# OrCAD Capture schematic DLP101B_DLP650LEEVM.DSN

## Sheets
1 PAGE-07 Important Notice
2 PAGE-06 Revisions
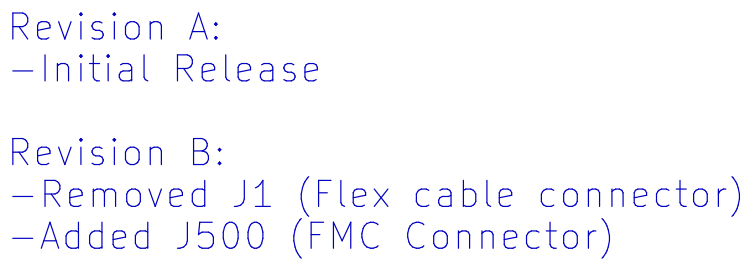
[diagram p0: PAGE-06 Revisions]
3 PAGE-05  DLPA200 Reset Driver: size A3
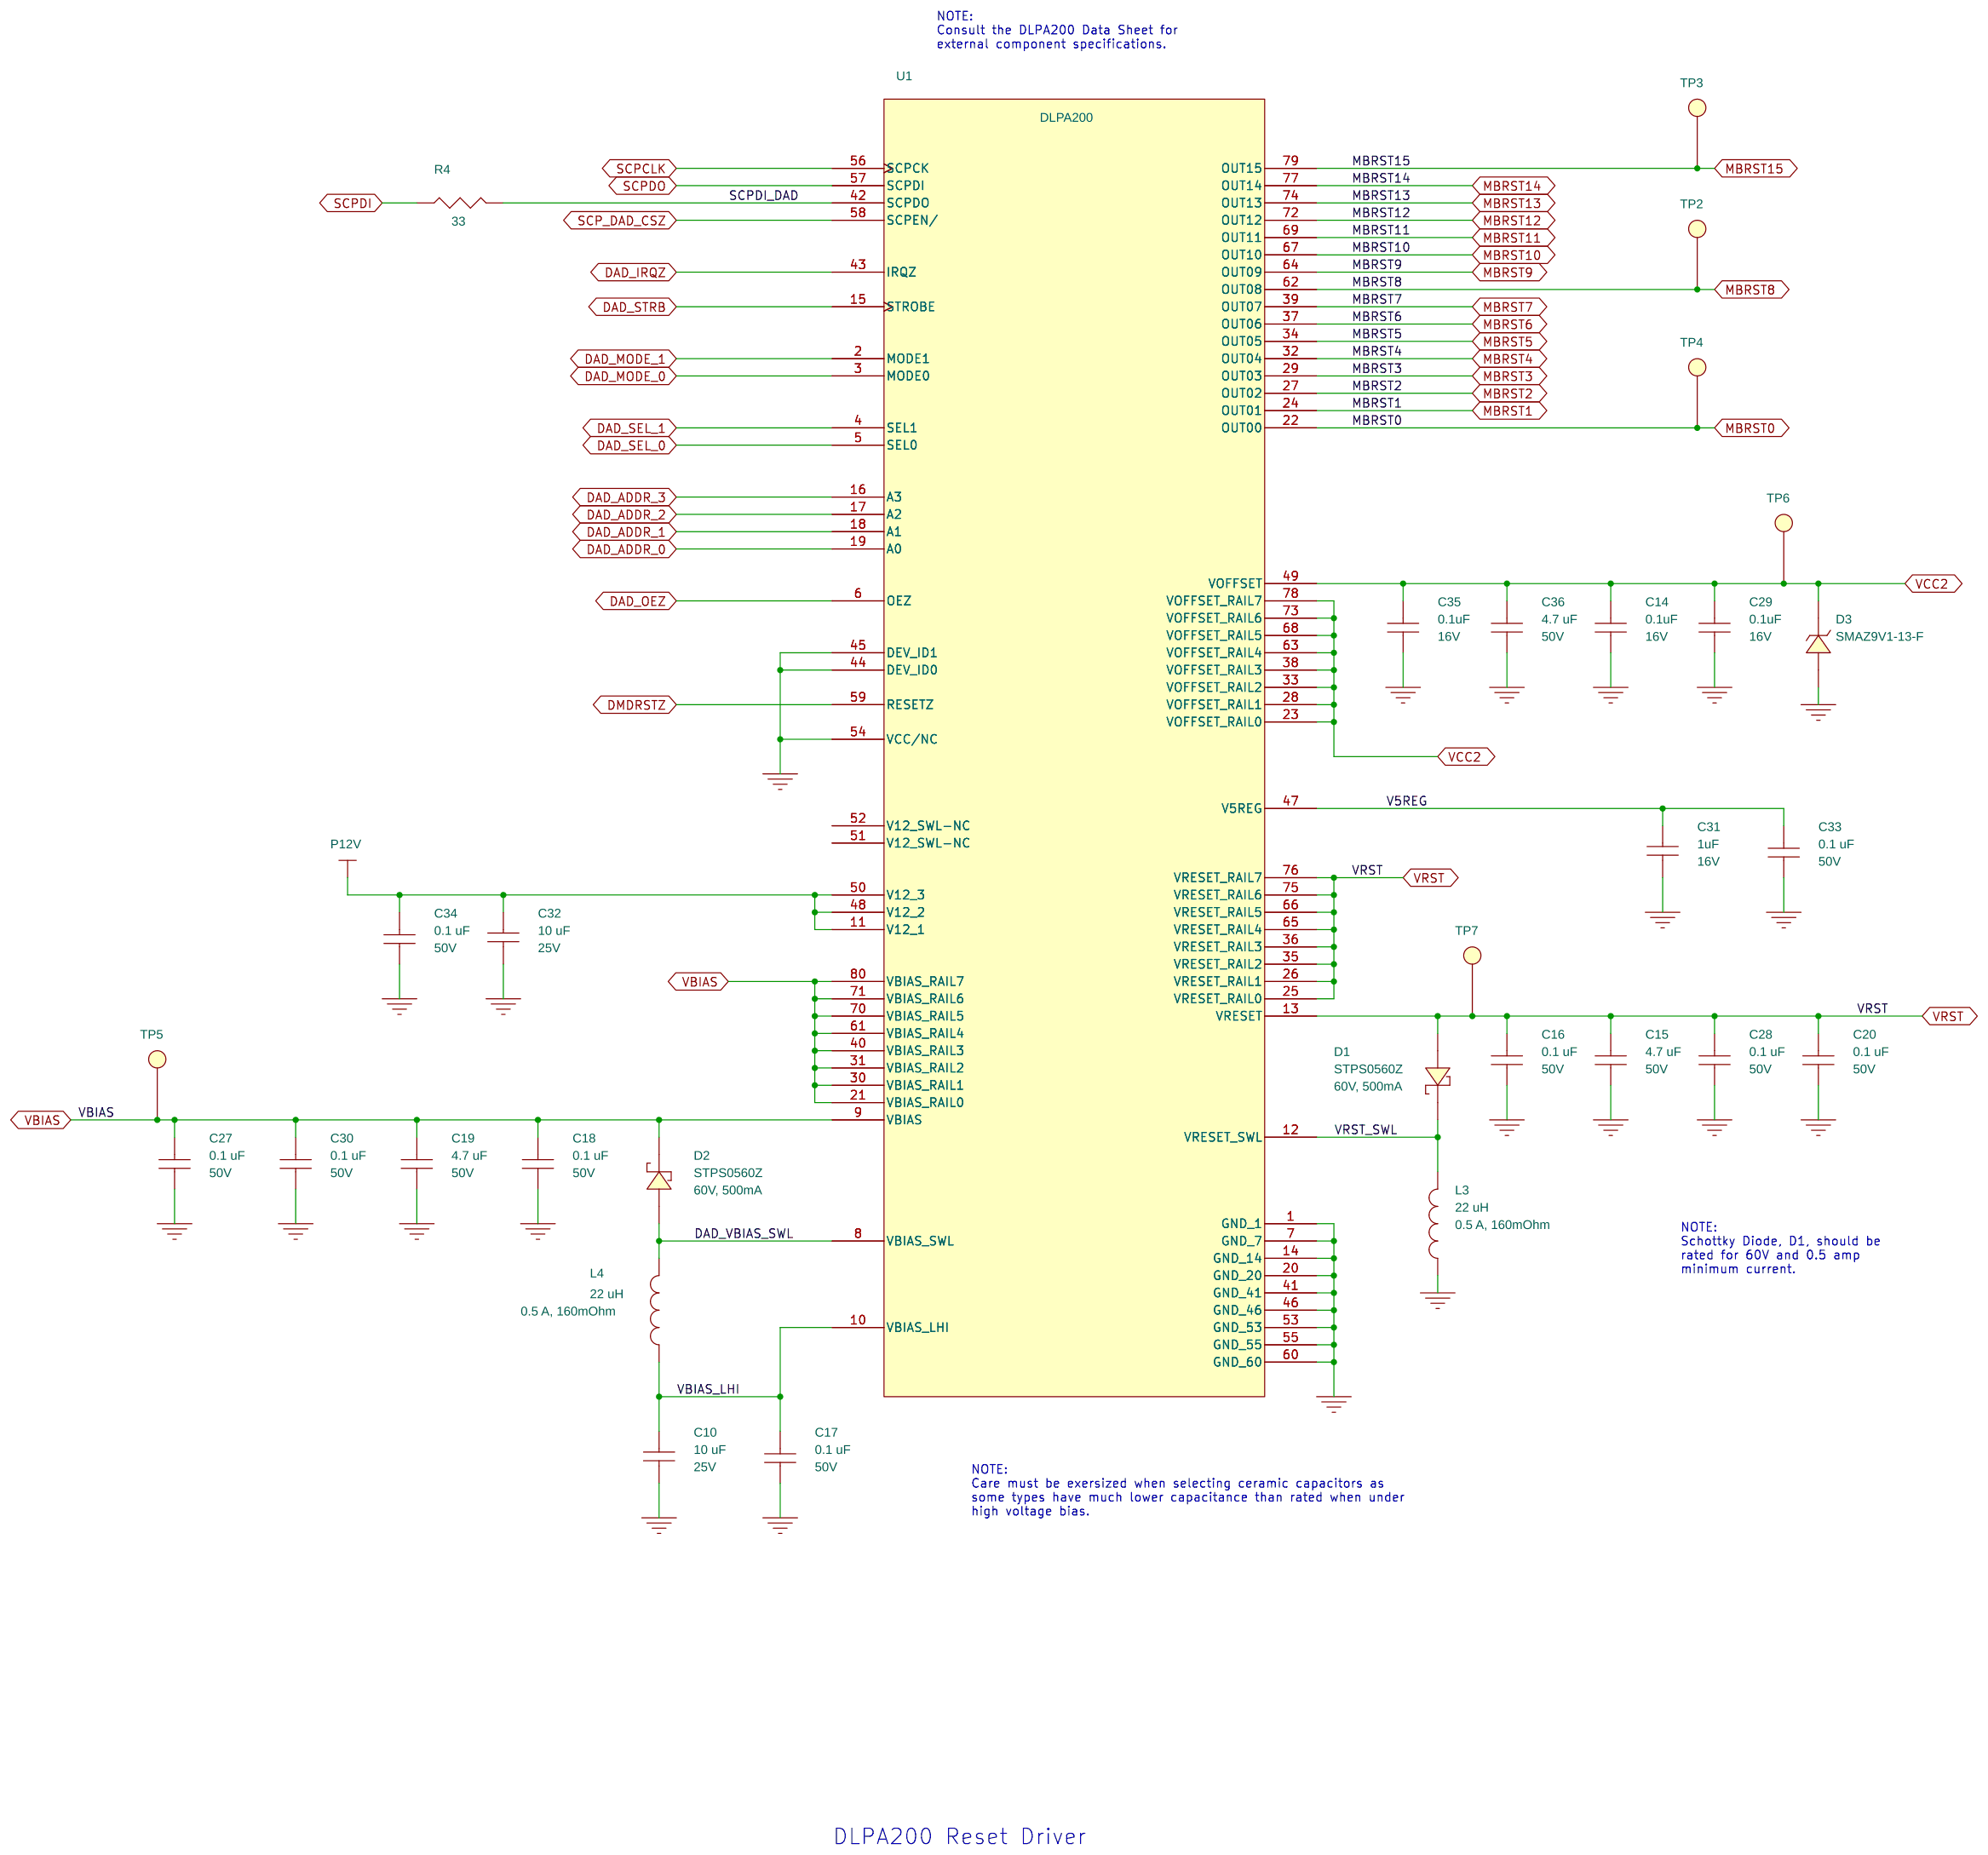
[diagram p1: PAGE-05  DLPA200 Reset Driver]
4 PAGE-01  TITLE: rev: D
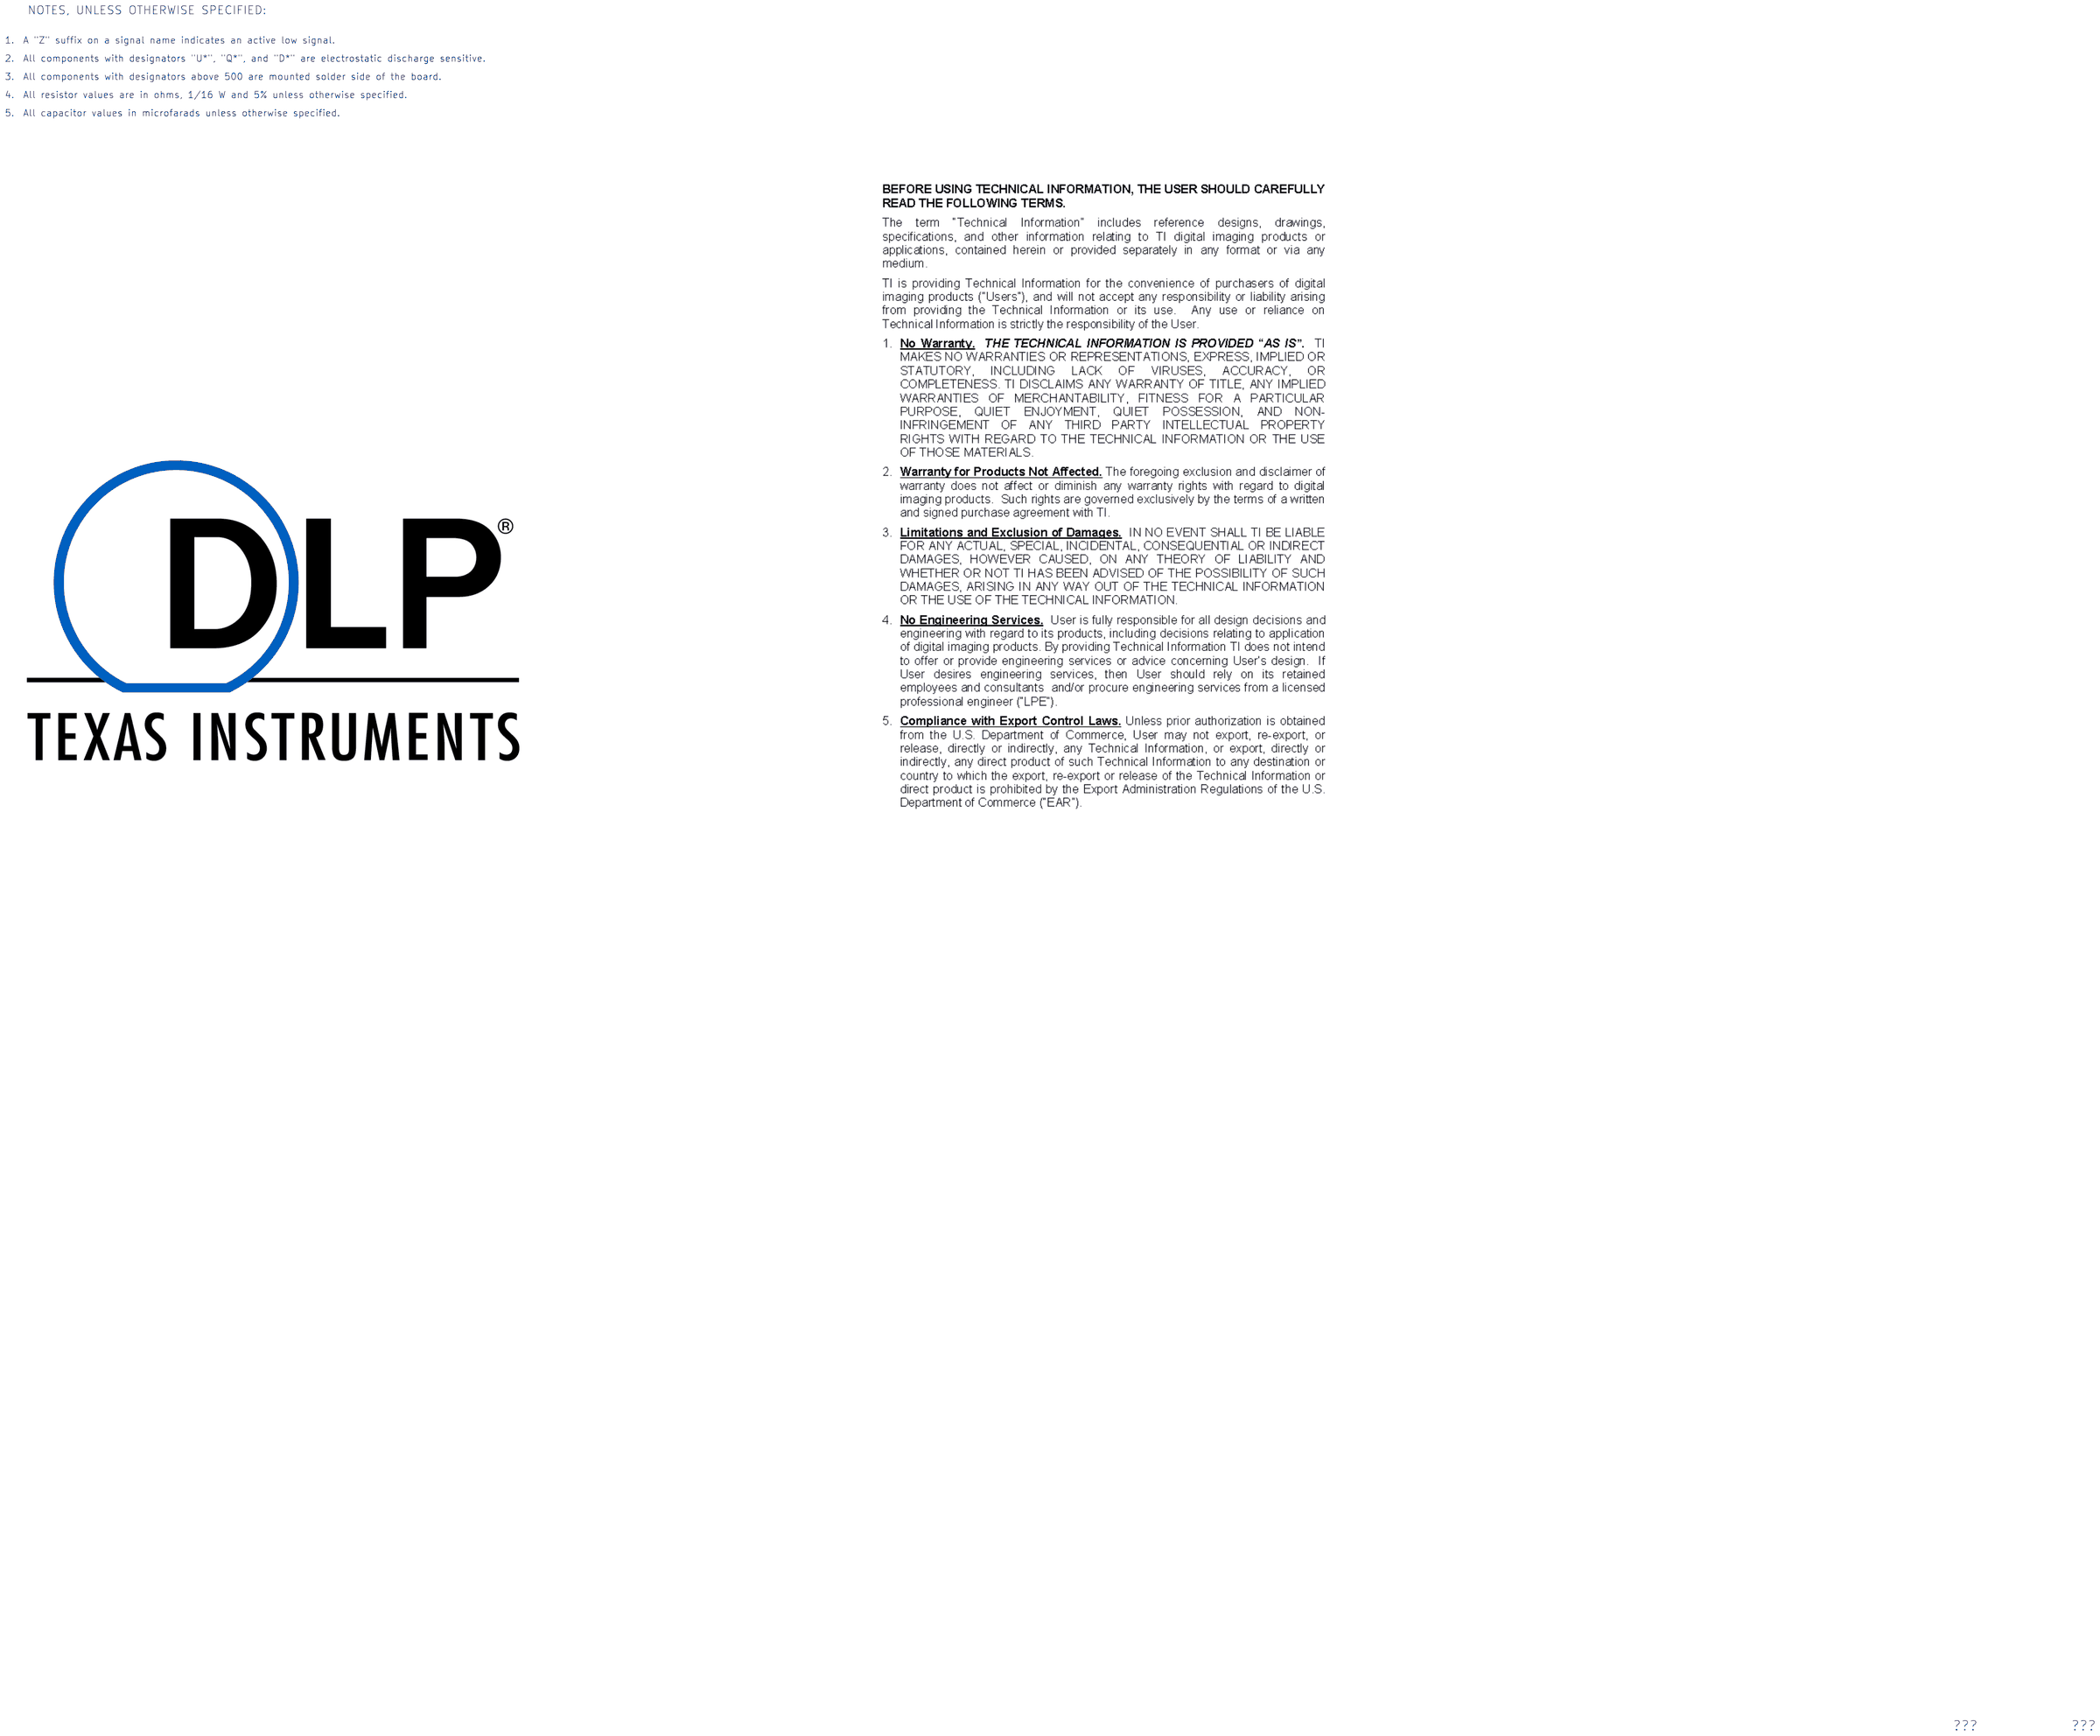
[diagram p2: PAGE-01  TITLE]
5 PAGE-02  Block Diagram
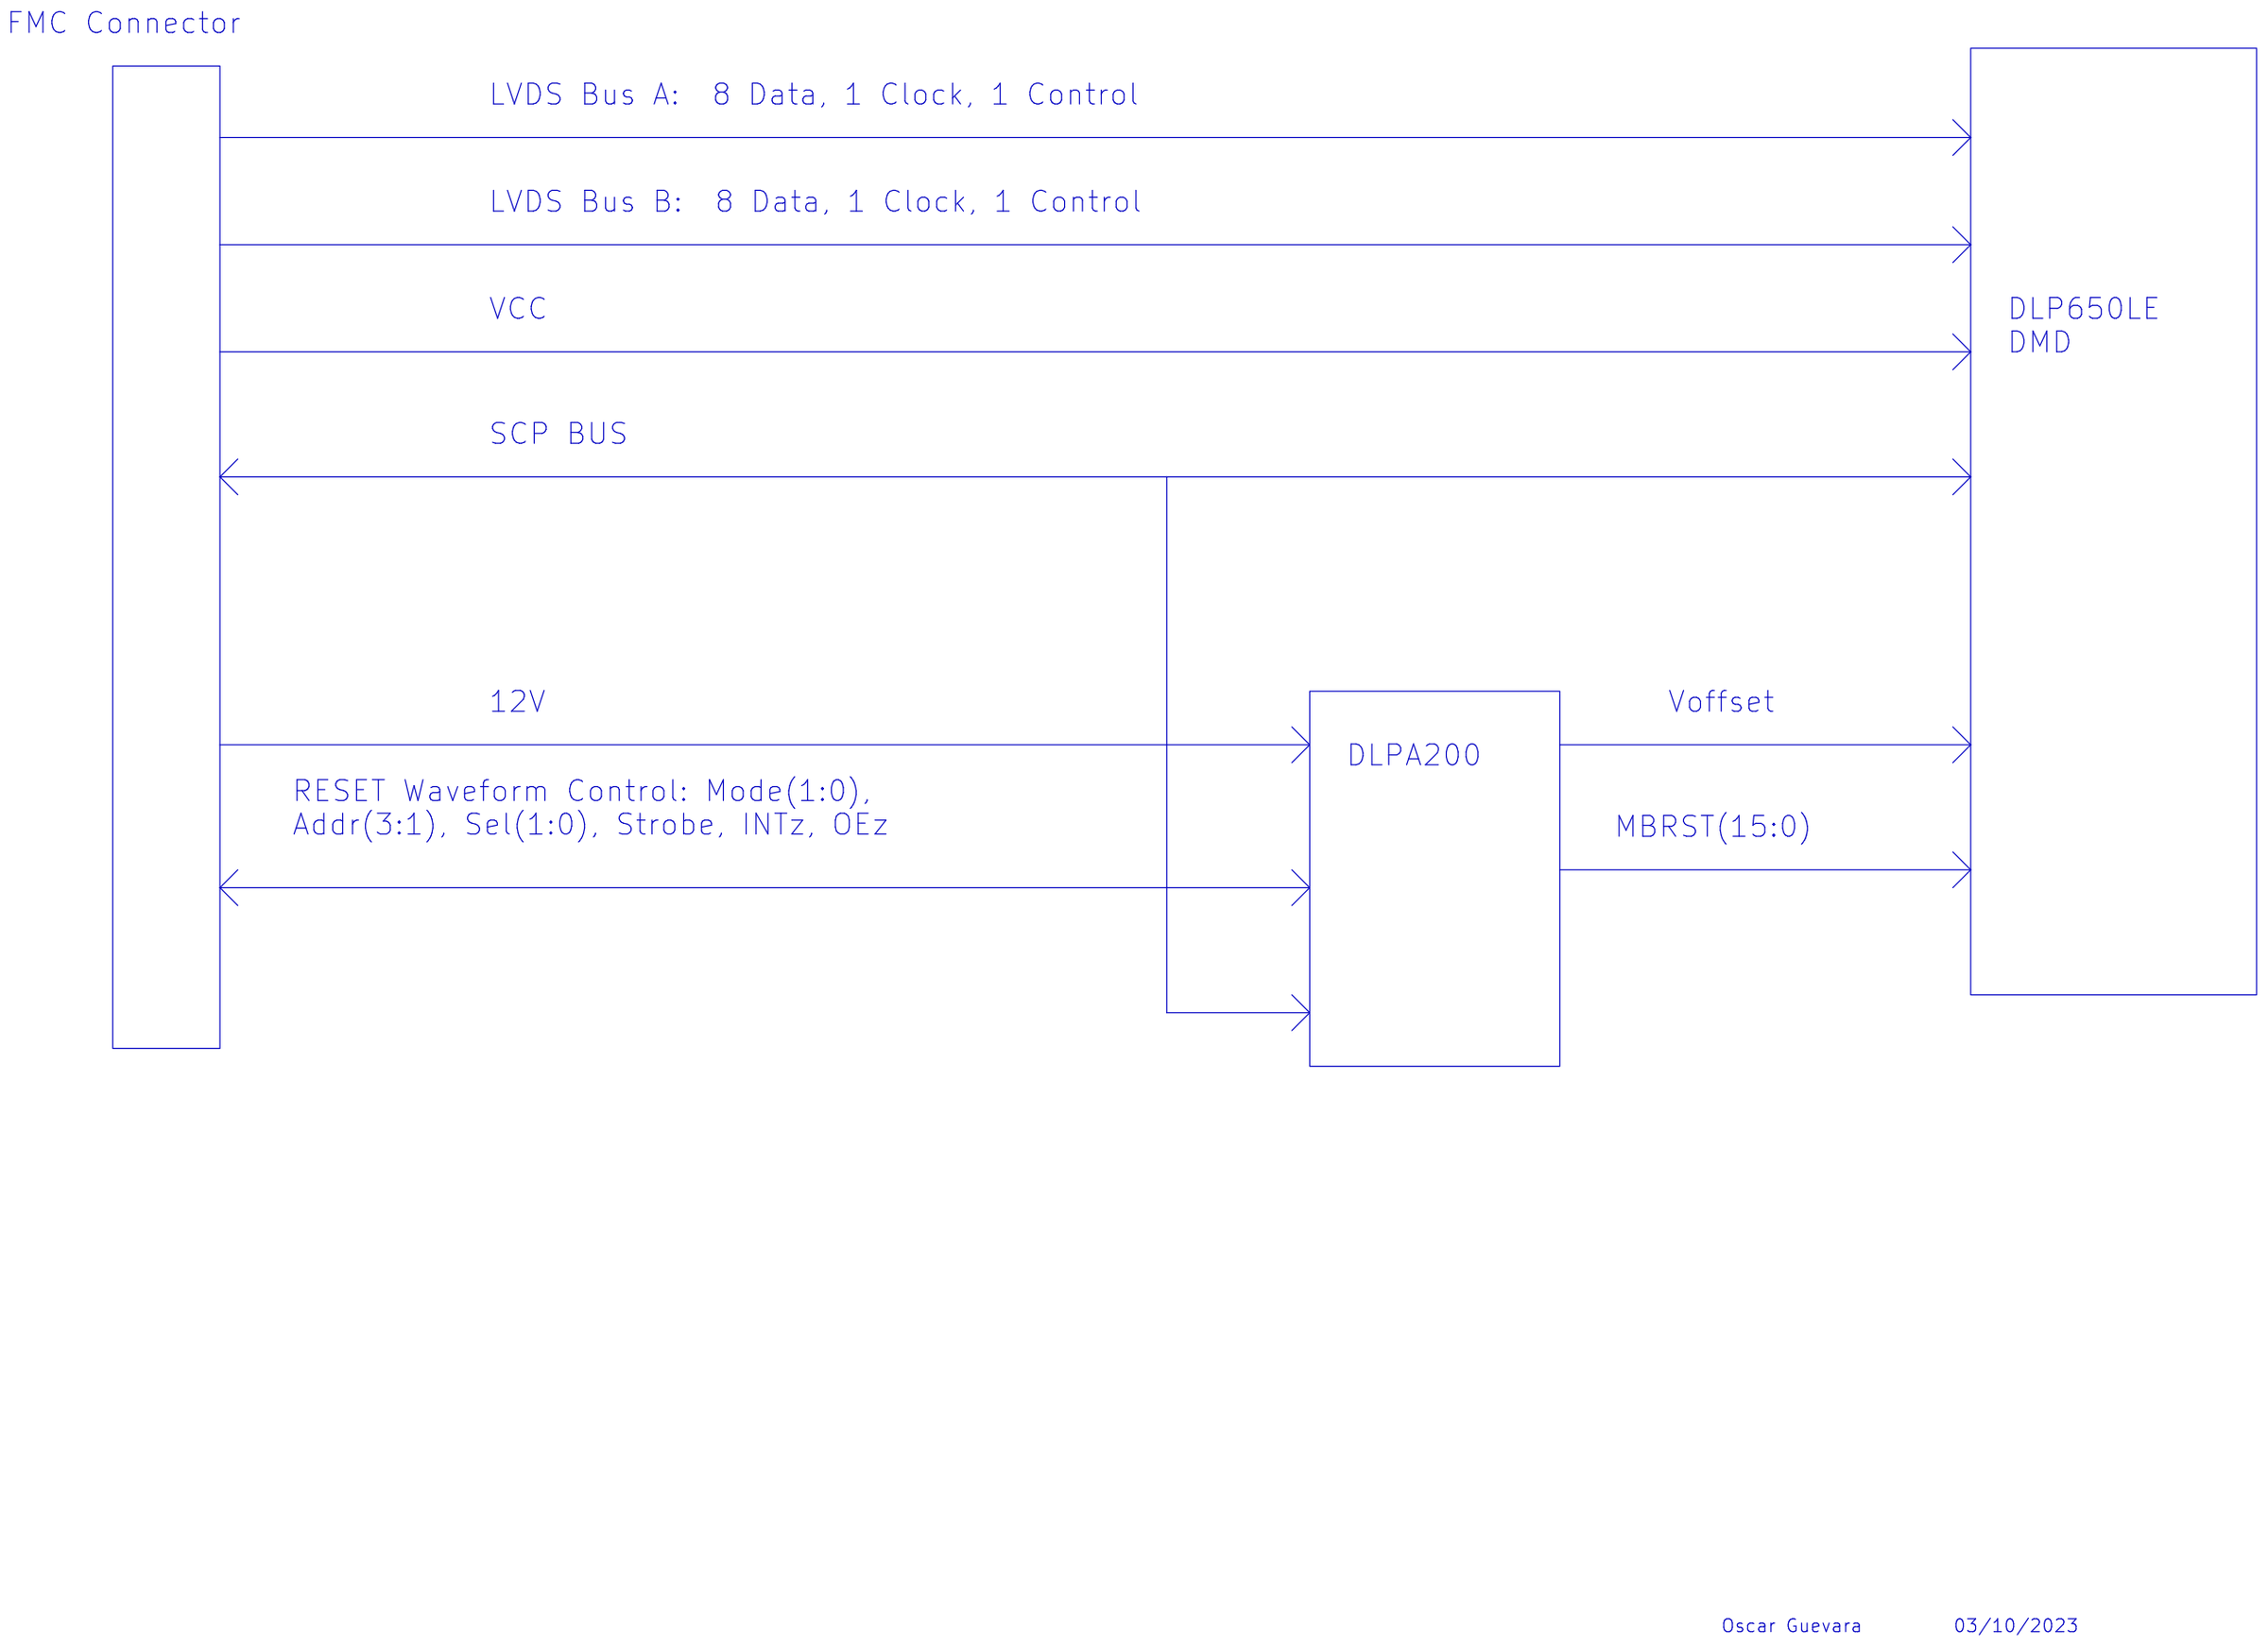
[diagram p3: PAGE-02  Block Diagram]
6 PAGE-04  Series 450 DMD: size A3
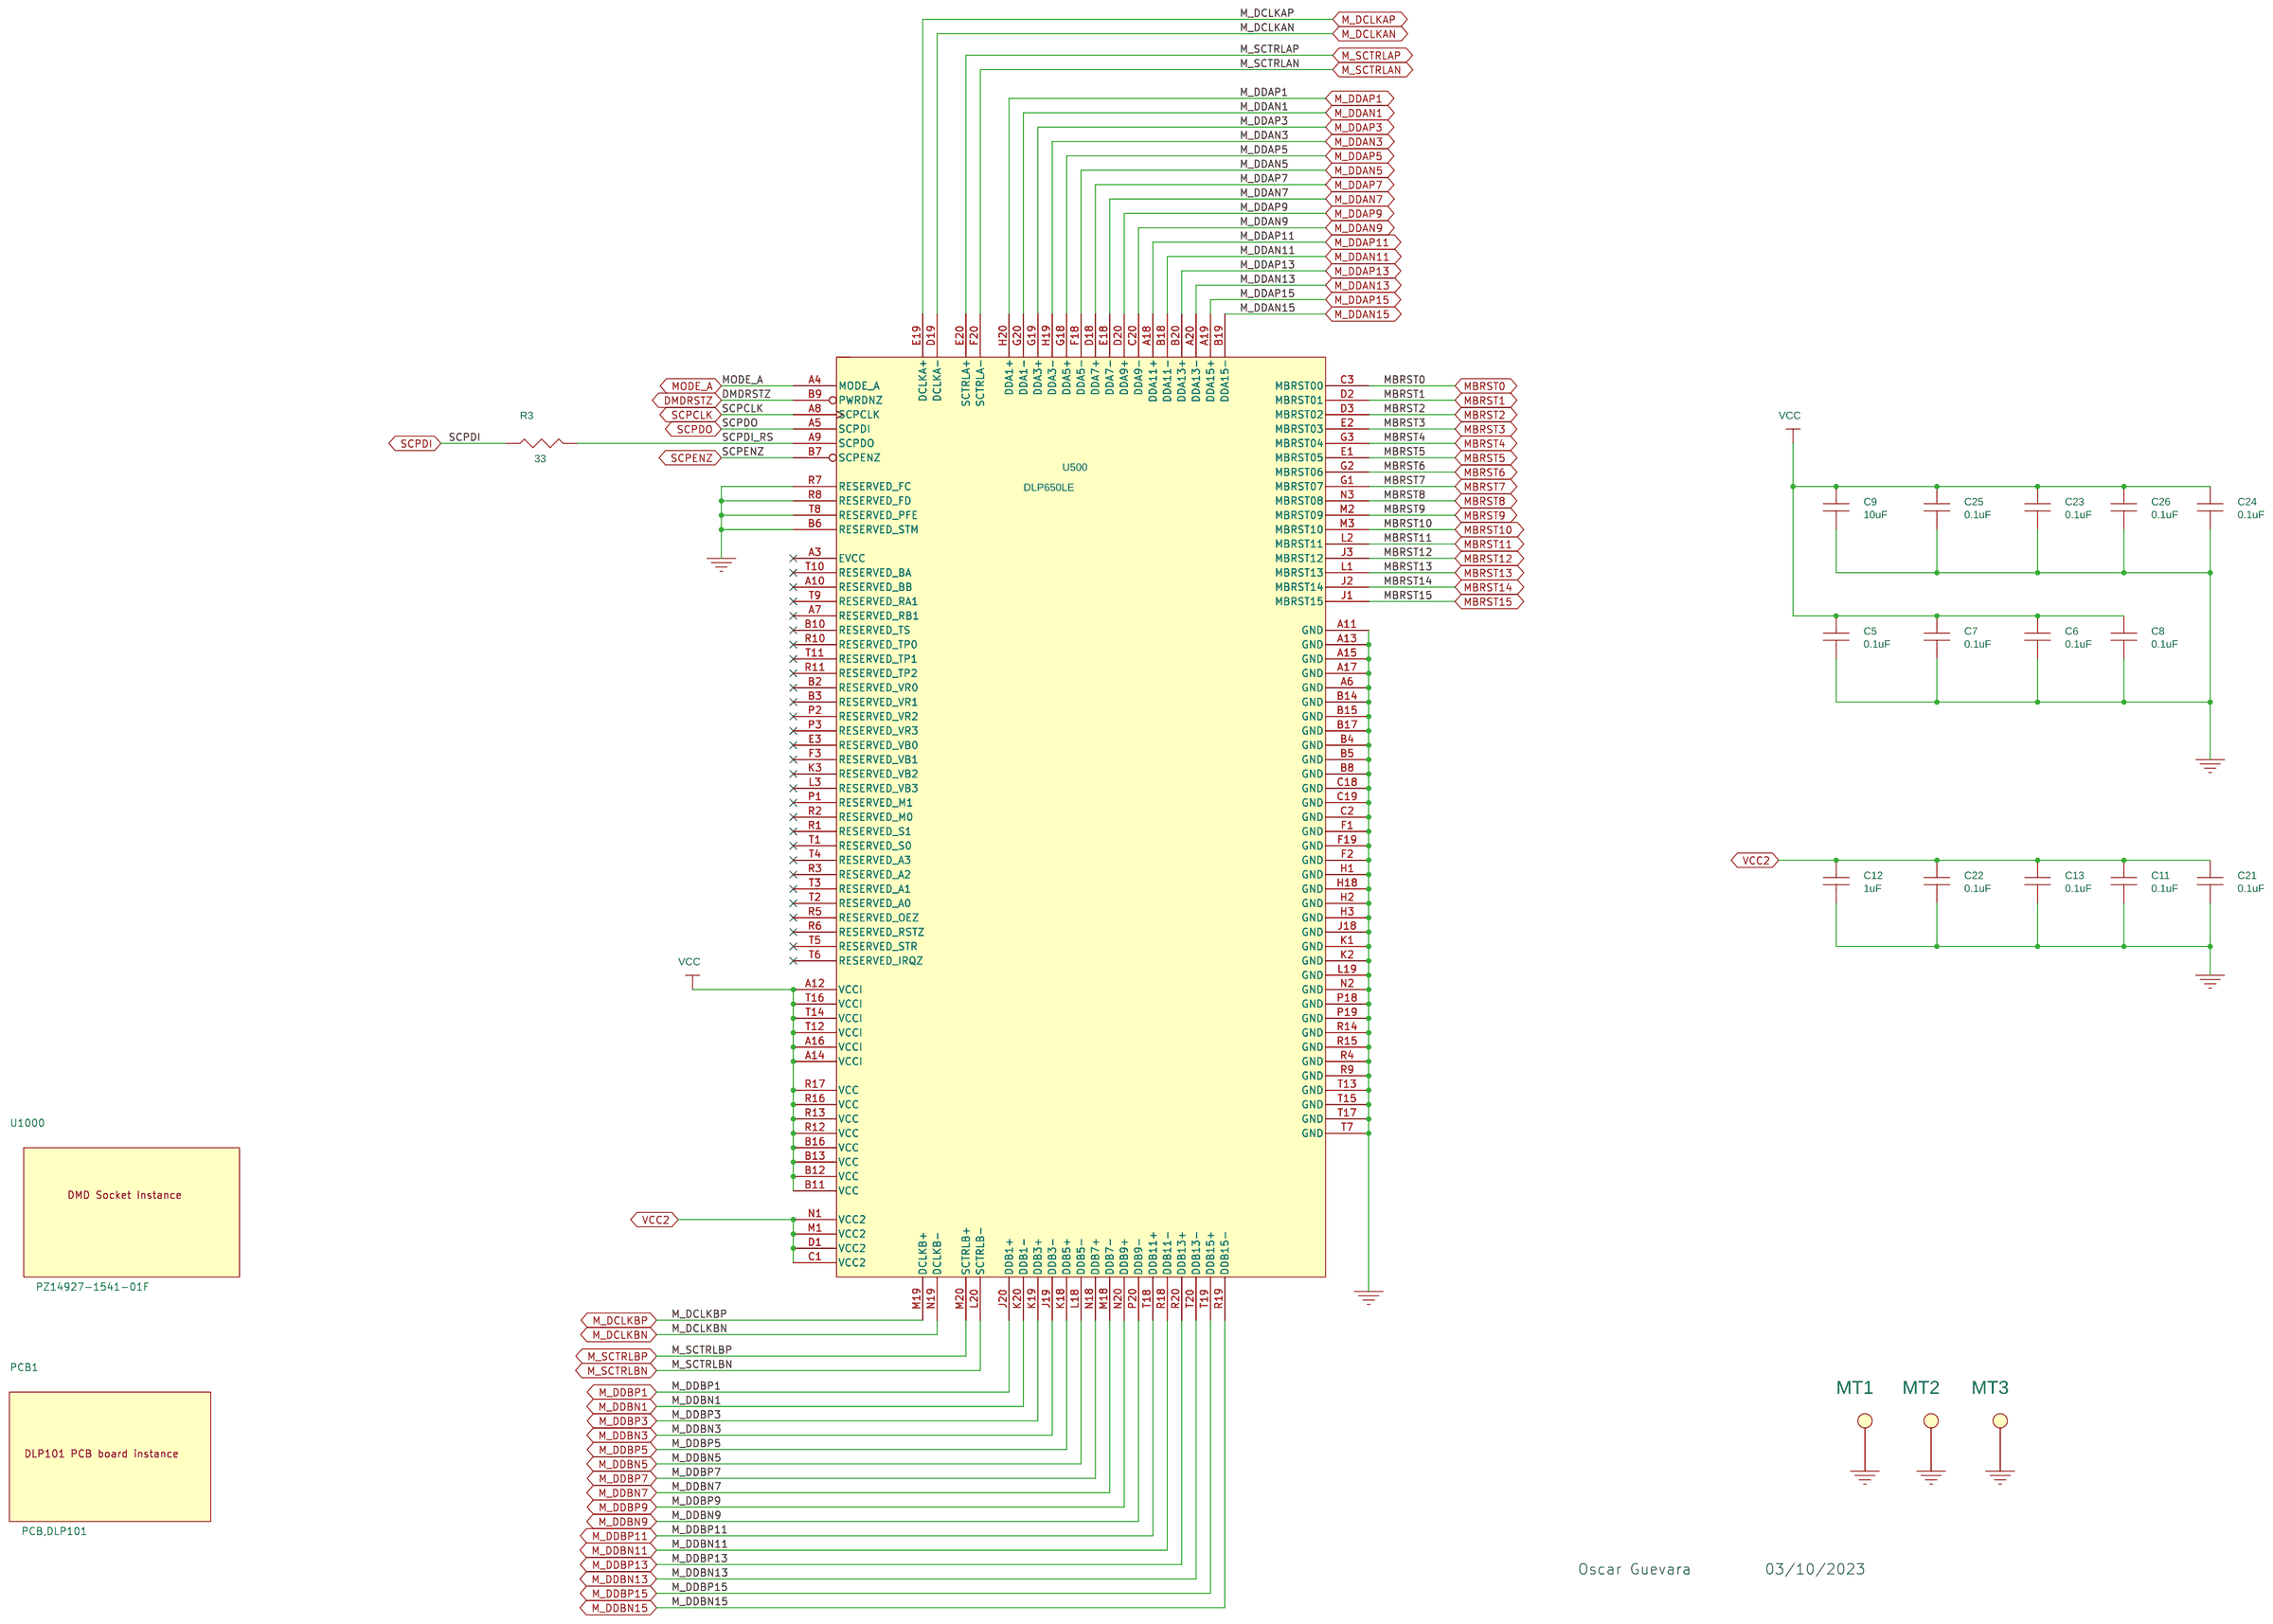
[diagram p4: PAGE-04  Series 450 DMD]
7 PAGE-03  FMC Connector: size A2
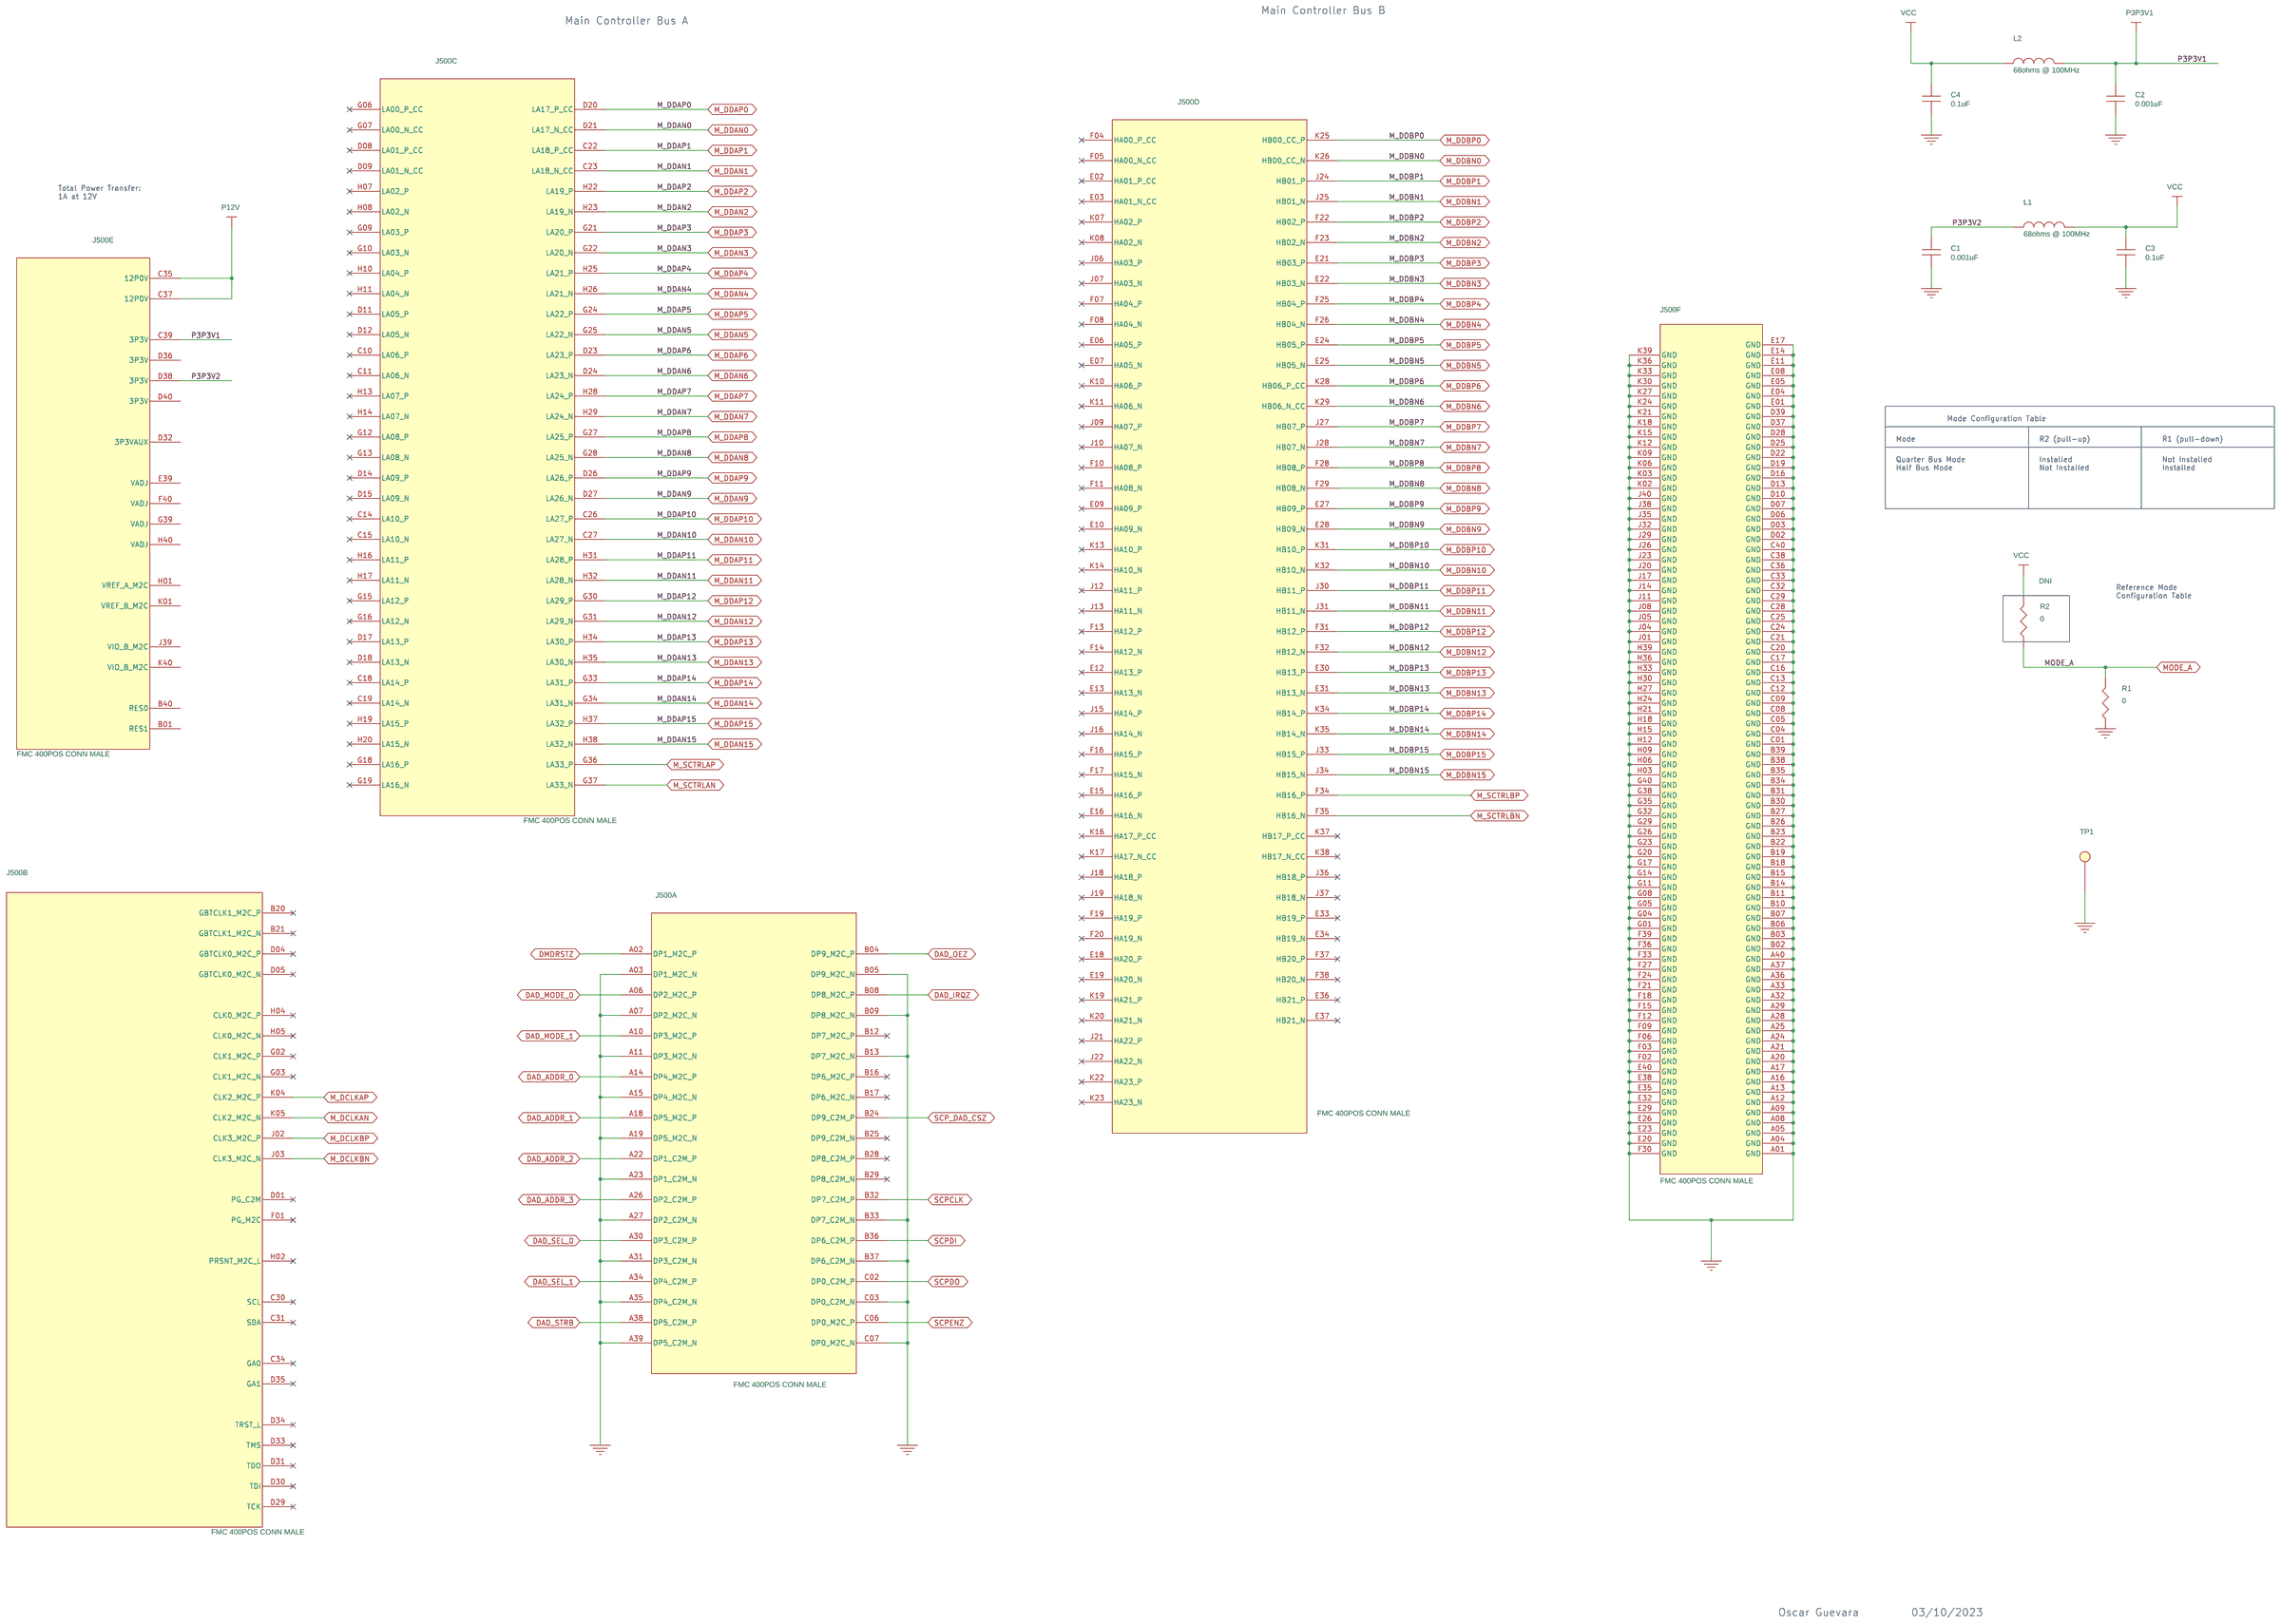
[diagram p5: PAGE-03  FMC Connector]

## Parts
sheet PAGE-03  FMC Connector
C1  0.001uF  [0603AVX]
C2  0.001uF  [0603AVX]
C3  0.1uF  [0603AVX]
C4  0.1uF  [0603AVX]
J500  FMC 400POS CONN MALE  [CONN400-SEAM-40-A-A_SAM-ALPHA]  (sections A,B,C,D,E,F)
L1  68ohms @ 100MHz  [0603AVX]
L2  68ohms @ 100MHz  [0603AVX]
R1  0  [0603AVX]
R2  0  [0603AVX]
TP1  Testpoint  [TP40_24]
sheet PAGE-04  Series 450 DMD
C5  0.1uF  [0603AVX]
C6  0.1uF  [0603AVX]
C7  0.1uF  [0603AVX]
C8  0.1uF  [0603AVX]
C9  10uF  [1206AVX]
C11  0.1uF  [0603AVX]
C12  1uF  [0603AVX]
C13  0.1uF  [0603AVX]
C21  0.1uF  [0603AVX]
C22  0.1uF  [0603AVX]
C23  0.1uF  [0603AVX]
C24  0.1uF  [0603AVX]
C25  0.1uF  [0603AVX]
C26  0.1uF  [0603AVX]
MT1  MT2  [MT2]
MT2  MT2  [MT2]
MT3  MT2  [MT2]
PCB1  PCB,DLP101
R3  33  [0603AVX]
U500  DLP650LE  [DMD_S450]
U1000  PZ14927-1541-01F  [DMD_S450]
sheet PAGE-05  DLPA200 Reset Driver
C10  10 uF  [CAP_1210]
C14  0.1uF  [0603AVX]
C15  4.7 uF  [CAP_1812]
C16  0.1 uF  [CAP_0805]
C17  0.1 uF  [CAP_0805]
C18  0.1 uF  [CAP_0805]
C19  4.7 uF  [CAP_1812]
C20  0.1 uF  [CAP_0805]
C27  0.1 uF  [CAP_0805]
C28  0.1 uF  [CAP_0805]
C29  0.1uF  [0603AVX]
C30  0.1 uF  [CAP_0805]
C31  1uF  [0603AVX]
C32  10 uF  [CAP_1210]
C33  0.1 uF  [CAP_0805]
C34  0.1 uF  [CAP_0805]
C35  0.1uF  [0603AVX]
C36  4.7 uF  [CAP_1812]
D1  DIODE_SCHOTTKY  [SOD_123]
D2  DIODE_SCHOTTKY  [SOD_123]
D3  9.1V  [DO-214AC]
L3  22 uH  [IND_DT1608C]
L4  22 uH  [IND_DT1608C]
R4  33  [0603AVX]
TP2  Testpoint  [TP40_24]
TP3  Testpoint  [TP40_24]
TP4  Testpoint  [TP40_24]
TP5  Testpoint  [TP40_24]
TP6  Testpoint  [TP40_24]
TP7  Testpoint  [TP40_24]
U1  DLPA200  [TQFP80_5MM]

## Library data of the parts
C1 C2 = CAP_NP: Capacitor; CCA ITEM: 3; MFG: AVX; Part Number: 06035C102KAT2A; Rating: 50V; Tolerance: 10%; Type: X7R
C3-C8 C11 C13 C21-C26 = CAP_NP: Capacitor; CCA ITEM: 1; MFG: AVX; Part Number: 0603YC104KAT2A; Rating: 16V; Tolerance: 10%; Type: X7R
J500 = FMC_400POS_CONNECTOR: MFG: Samtec; PART NUMBER: SEAM-40-11.0-S-10-2-A-K-TR
L1 L2 = INDUCTOR: Ferrite; CCA ITEM: 11; MFG: Steward; Part Number: MI0603J680R-10
R1 = R: Resistor; CCA ITEM: 14; MFG: Yageo; Part Number: RC0603JR-070RL; Rating: 1/10W
R2 = R: Resistor; CCA ITEM: 14; MFG: Yageo; Note: DNI; Part Number: RC0603JR-070RL; Rating: 1/10W
TP1-TP7 = Testpoint: Test point
C9 = CAP_NP: Capacitor; CCA ITEM: 7; MFG: Samsung Electro-Mechanics; Part Number: CL31B106KAHNNNE; Rating: 25V; Tolerance: 10%; Type: X7R
C12 = CAP_NP: Capacitor; CCA ITEM: 6; MFG: Samsung Electro-Mechanics; Part Number: CL10B105KO8NNNC; Rating: 16V; Tolerance: 10%; Type: X7R
MT1-MT3 = Testpoint: Test point; DNI: DNI
PCB1 = DLP026_5
R3 R4 = R: Resistor; CCA ITEM: 13; MFG: Yageo; Part Number: RC0603FR-0733RL; Rating: 1/10W; Tolerance: 1%
U500 = Series_450_DMD: IC, S450 DMD Socket; CCA ITEM: 15; MFG: TI
U1000 = DLP026_4: MFG: Foxconn
C10 C32 = CAP_NP: Capacitor; CCA ITEM: 4; MFG: TDK; Part Number: C3225X7R1E106M; RATING: 25V; TOLERANCE: 20%; Type: X7R
C14 C29 C35 = CAP_NP: Capacitor; CCA ITEM: 1; MFG: AVX; Part Number: 0603YC104KAT2A; RATING: 16V; TOLERANCE: 10%; Type: X7R
C15 C19 C36 = CAP_NP: Capacitor; CCA ITEM: 5; MFG: TDK; Part Number: C4532X7R1H475M; RATING: 50V; TOLERANCE: 20%; Type: X7R
C16-C18 C20 C27 C28 C30 C33 C34 = CAP_NP: Capacitor; CCA ITEM: 2; MFG: AVX; Part Number: 08055C104MAT2A; RATING: 50V; TOLERANCE: 20%; Type: X7R
C31 = CAP_NP: Capacitor; CCA ITEM: 6; MFG: Samsung Electro-Mechanics; Part Number: CL10B105KO8NNNC; RATING: 16V; TOLERANCE: 10%; Type: X7R
D1 D2 = DIODE_SCHOTTKY: Diode, Schottky; CCA ITEM: 10; MFG: STMICRO; Part Number: STPS0560Z; RATING: 60V, 500mA
D3 = DIODE_ZENER: Diode, Zener; CCA ITEM: 9; MFG: DIODES INC; Part Number: SMAZ9V1-13-F; RATING: 1W; RATING/TOLERANCE: 5%; Tolerance: 5%
L3 L4 = INDUCTOR: Inductor; CCA ITEM: 12; ICA_MFR_NAME: STEWARD; ICA_PARTNUM: $$731362$$MI0603J680R-10; MFG: COILCRAFT; Part Number: DT1608C-223; RATING: 0.5 A, 160mOhm
U1 = DAD2000: IC, DMD Power and Reset; CCA ITEM: 16; MFG: TI

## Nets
GND: C1.2 C2.2 C3.2 C4.2 C5.2 C6.2 C7.2 C8.2 C9.2 C10.2 C11.2 C12.2 C13.2 C14.1 C15.1 C16.1 C17.1 C18.1 C19.1 C20.1 C21.2 C22.2 C23.2 C24.2 C25.2 C26.2 C27.1 C28.1 C29.1 C30.1 C31.2 C32.2 C33.1 C34.1 C35.1 C36.1 D3.2(ANODE) J500.A01(GND) J500.A03(DP1_M2C_N) J500.A04(GND) J500.A05(GND) J500.A07(DP2_M2C_N) J500.A08(GND) J500.A09(GND) J500.A11(DP3_M2C_N) J500.A12(GND) J500.A13(GND) J500.A15(DP4_M2C_N) J500.A16(GND) J500.A17(GND) J500.A19(DP5_M2C_N) J500.A20(GND) J500.A21(GND) J500.A23(DP1_C2M_N) J500.A24(GND) J500.A25(GND) J500.A27(DP2_C2M_N) J500.A28(GND) J500.A29(GND) J500.A31(DP3_C2M_N) J500.A32(GND) J500.A33(GND) J500.A35(DP4_C2M_N) J500.A36(GND) J500.A37(GND) J500.A39(DP5_C2M_N) J500.A40(GND) J500.B02(GND) J500.B03(GND) J500.B05(DP9_M2C_N) J500.B06(GND) J500.B07(GND) J500.B09(DP8_M2C_N) J500.B10(GND) J500.B11(GND) J500.B13(DP7_M2C_N) J500.B14(GND) J500.B15(GND) J500.B18(GND) J500.B19(GND) J500.B22(GND) J500.B23(GND) J500.B26(GND) J500.B27(GND) J500.B30(GND) J500.B31(GND) J500.B33(DP7_C2M_N) J500.B34(GND) J500.B35(GND) J500.B37(DP6_C2M_N) J500.B38(GND) J500.B39(GND) J500.C01(GND) J500.C03(DP0_C2M_N) J500.C04(GND) J500.C05(GND) J500.C07(DP0_M2C_N) J500.C08(GND) J500.C09(GND) J500.C12(GND) J500.C13(GND) J500.C16(GND) J500.C17(GND) J500.C20(GND) J500.C21(GND) J500.C24(GND) J500.C25(GND) J500.C28(GND) J500.C29(GND) J500.C32(GND) J500.C33(GND) J500.C36(GND) J500.C38(GND) J500.C40(GND) J500.D02(GND) J500.D03(GND) J500.D06(GND) J500.D07(GND) J500.D10(GND) J500.D13(GND) J500.D16(GND) J500.D19(GND) J500.D22(GND) J500.D25(GND) J500.D28(GND) J500.D37(GND) J500.D39(GND) J500.E01(GND) J500.E04(GND) J500.E05(GND) J500.E08(GND) J500.E11(GND) J500.E14(GND) J500.E17(GND) J500.E20(GND) J500.E23(GND) J500.E26(GND) J500.E29(GND) J500.E32(GND) J500.E35(GND) J500.E38(GND) J500.E40(GND) J500.F02(GND) J500.F03(GND) J500.F06(GND) J500.F09(GND) J500.F12(GND) J500.F15(GND) J500.F18(GND) J500.F21(GND) J500.F24(GND) J500.F27(GND) J500.F30(GND) J500.F33(GND) J500.F36(GND) J500.F39(GND) J500.G01(GND) J500.G04(GND) J500.G05(GND) J500.G08(GND) J500.G11(GND) J500.G14(GND) J500.G17(GND) J500.G20(GND) J500.G23(GND) J500.G26(GND) J500.G29(GND) J500.G32(GND) J500.G35(GND) J500.G38(GND) J500.G40(GND) J500.H03(GND) J500.H06(GND) J500.H09(GND) J500.H12(GND) J500.H15(GND) J500.H18(GND) J500.H21(GND) J500.H24(GND) J500.H27(GND) J500.H30(GND) J500.H33(GND) J500.H36(GND) J500.H39(GND) J500.J01(GND) J500.J04(GND) J500.J05(GND) J500.J08(GND) J500.J11(GND) J500.J14(GND) J500.J17(GND) J500.J20(GND) J500.J23(GND) J500.J26(GND) J500.J29(GND) J500.J32(GND) J500.J35(GND) J500.J38(GND) J500.J40(GND) J500.K02(GND) J500.K03(GND) J500.K06(GND) J500.K09(GND) J500.K12(GND) J500.K15(GND) J500.K18(GND) J500.K21(GND) J500.K24(GND) J500.K27(GND) J500.K30(GND) J500.K33(GND) J500.K36(GND) J500.K39(GND) L3.1 MT1.1 MT2.1 MT3.1 R1.1 TP1.1 U1.1(GND) U1.7(GND) U1.14(GND) U1.20(GND) U1.41(GND) U1.44(DEV_ID0) U1.45(DEV_ID1) U1.46(GND) U1.53(GND) U1.54(VCC/NC) U1.55(GND) U1.60(GND) U500.A6(GND) U500.A11(GND) U500.A13(GND) U500.A15(GND) U500.A17(GND) U500.B4(GND) U500.B5(GND) U500.B6(RESERVED_STM) U500.B8(GND) U500.B14(GND) U500.B15(GND) U500.B17(GND) U500.C2(GND) U500.C18(GND) U500.C19(GND) U500.F1(GND) U500.F2(GND) U500.F19(GND) U500.H1(GND) U500.H2(GND) U500.H3(GND) U500.H18(GND) U500.J18(GND) U500.K1(GND) U500.K2(GND) U500.L19(GND) U500.N2(GND) U500.P18(GND) U500.P19(GND) U500.R4(GND) U500.R7(RESERVED_FC) U500.R8(RESERVED_FD) U500.R9(GND) U500.R14(GND) U500.R15(GND) U500.T7(GND) U500.T8(RESERVED_PFE) U500.T13(GND) U500.T15(GND) U500.T17(GND)
P12V: C32.1 C34.2 J500.C35(12P0V) J500.C37(12P0V) U1.11(V12_1) U1.48(V12_2) U1.50(V12_3)
V5REG: C31.1 C33.2 U1.47(V5REG)
V12_SWL-NC: U1.51(V12_SWL-NC) U1.52(V12_SWL-NC)
VCC: C3.1 C4.1 C5.1 C6.1 C7.1 C8.1 C9.1 C23.1 C24.1 C25.1 C26.1 L1.2 L2.1 R2.2 U500.A12(VCCI) U500.A14(VCCI) U500.A16(VCCI) U500.B11(VCC) U500.B12(VCC) U500.B13(VCC) U500.B16(VCC) U500.R12(VCC) U500.R13(VCC) U500.R16(VCC) U500.R17(VCC) U500.T12(VCCI) U500.T14(VCCI) U500.T16(VCCI)
VCC2: C11.1 C12.1 C13.1 C14.2 C21.1 C22.1 C29.2 C35.2 C36.2 D3.1(CATHODE) TP6.1 U1.23(VOFFSET_RAIL0) U1.28(VOFFSET_RAIL1) U1.33(VOFFSET_RAIL2) U1.38(VOFFSET_RAIL3) U1.49(VOFFSET) U1.63(VOFFSET_RAIL4) U1.68(VOFFSET_RAIL5) U1.73(VOFFSET_RAIL6) U1.78(VOFFSET_RAIL7) U500.C1(VCC2) U500.D1(VCC2) U500.M1(VCC2) U500.N1(VCC2)
3P3V: C2.1 J500.C39(3P3V) J500.D36(3P3V) J500.D40(3P3V) L2.2
3P3VAUX: J500.D32(3P3VAUX)
DAD_ADDR_0: J500.A14(DP4_M2C_P) U1.19(A0)
DAD_ADDR_1: J500.A18(DP5_M2C_P) U1.18(A1)
DAD_ADDR_2: J500.A22(DP1_C2M_P) U1.17(A2)
DAD_ADDR_3: J500.A26(DP2_C2M_P) U1.16(A3)
DAD_IRQZ: J500.B08(DP8_M2C_P) U1.43(IRQZ)
DAD_MODE_0: J500.A06(DP2_M2C_P) U1.3(MODE0)
DAD_MODE_1: J500.A10(DP3_M2C_P) U1.2(MODE1)
DAD_OEZ: J500.B04(DP9_M2C_P) U1.6(OEZ)
DAD_SEL_0: J500.A30(DP3_C2M_P) U1.5(SEL0)
DAD_SEL_1: J500.A34(DP4_C2M_P) U1.4(SEL1)
DAD_STRB: J500.A38(DP5_C2M_P) U1.15(STROBE)
DAD_VBIAS_SWL: D2.2(A) L4.2 U1.8(VBIAS_SWL)
DMDRSTZ: J500.A02(DP1_M2C_P) U1.59(RESETZ) U500.B9(PWRDNZ)
M_DCLKAN: J500.K05(CLK2_M2C_N) U500.D19(DCLKA-)
M_DCLKAP: J500.K04(CLK2_M2C_P) U500.E19(DCLKA+)
M_DCLKBN: J500.J03(CLK3_M2C_N) U500.N19(DCLKB-)
M_DCLKBP: J500.J02(CLK3_M2C_P) U500.M19(DCLKB+)
M_DDAN0: J500.D21(LA17_N_CC)
M_DDAN1: J500.C23(LA18_N_CC) U500.G20(DDA1-)
M_DDAN2: J500.H23(LA19_N)
M_DDAN3: J500.G22(LA20_N) U500.H19(DDA3-)
M_DDAN4: J500.H26(LA21_N)
M_DDAN5: J500.G25(LA22_N) U500.F18(DDA5-)
M_DDAN6: J500.D24(LA23_N)
M_DDAN7: J500.H29(LA24_N) U500.E18(DDA7-)
M_DDAN8: J500.G28(LA25_N)
M_DDAN9: J500.D27(LA26_N) U500.C20(DDA9-)
M_DDAN10: J500.C27(LA27_N)
M_DDAN11: J500.H32(LA28_N) U500.B18(DDA11-)
M_DDAN12: J500.G31(LA29_N)
M_DDAN13: J500.H35(LA30_N) U500.A20(DDA13-)
M_DDAN14: J500.G34(LA31_N)
M_DDAN15: J500.H38(LA32_N) U500.B19(DDA15-)
M_DDAP0: J500.D20(LA17_P_CC)
M_DDAP1: J500.C22(LA18_P_CC) U500.H20(DDA1+)
M_DDAP2: J500.H22(LA19_P)
M_DDAP3: J500.G21(LA20_P) U500.G19(DDA3+)
M_DDAP4: J500.H25(LA21_P)
M_DDAP5: J500.G24(LA22_P) U500.G18(DDA5+)
M_DDAP6: J500.D23(LA23_P)
M_DDAP7: J500.H28(LA24_P) U500.D18(DDA7+)
M_DDAP8: J500.G27(LA25_P)
M_DDAP9: J500.D26(LA26_P) U500.D20(DDA9+)
M_DDAP10: J500.C26(LA27_P)
M_DDAP11: J500.H31(LA28_P) U500.A18(DDA11+)
M_DDAP12: J500.G30(LA29_P)
M_DDAP13: J500.H34(LA30_P) U500.B20(DDA13+)
M_DDAP14: J500.G33(LA31_P)
M_DDAP15: J500.H37(LA32_P) U500.A19(DDA15+)
M_DDBN0: J500.K26(HB00_CC_N)
M_DDBN1: J500.J25(HB01_N) U500.K20(DDB1-)
M_DDBN2: J500.F23(HB02_N)
M_DDBN3: J500.E22(HB03_N) U500.J19(DDB3-)
M_DDBN4: J500.F26(HB04_N)
M_DDBN5: J500.E25(HB05_N) U500.L18(DDB5-)
M_DDBN6: J500.K29(HB06_N_CC)
M_DDBN7: J500.J28(HB07_N) U500.M18(DDB7-)
M_DDBN8: J500.F29(HB08_N)
M_DDBN9: J500.E28(HB09_N) U500.P20(DDB9-)
M_DDBN10: J500.K32(HB10_N)
M_DDBN11: J500.J31(HB11_N) U500.R18(DDB11-)
M_DDBN12: J500.F32(HB12_N)
M_DDBN13: J500.E31(HB13_N) U500.T20(DDB13-)
M_DDBN14: J500.K35(HB14_N)
M_DDBN15: J500.J34(HB15_N) U500.R19(DDB15-)
M_DDBP0: J500.K25(HB00_CC_P)
M_DDBP1: J500.J24(HB01_P) U500.J20(DDB1+)
M_DDBP2: J500.F22(HB02_P)
M_DDBP3: J500.E21(HB03_P) U500.K19(DDB3+)
M_DDBP4: J500.F25(HB04_P)
M_DDBP5: J500.E24(HB05_P) U500.K18(DDB5+)
M_DDBP6: J500.K28(HB06_P_CC)
M_DDBP7: J500.J27(HB07_P) U500.N18(DDB7+)
M_DDBP8: J500.F28(HB08_P)
M_DDBP9: J500.E27(HB09_P) U500.N20(DDB9+)
M_DDBP10: J500.K31(HB10_P)
M_DDBP11: J500.J30(HB11_P) U500.T18(DDB11+)
M_DDBP12: J500.F31(HB12_P)
M_DDBP13: J500.E30(HB13_P) U500.R20(DDB13+)
M_DDBP14: J500.K34(HB14_P)
M_DDBP15: J500.J33(HB15_P) U500.T19(DDB15+)
M_SCTRLAN: J500.G37(LA33_N) U500.F20(SCTRLA-)
M_SCTRLAP: J500.G36(LA33_P) U500.E20(SCTRLA+)
M_SCTRLBN: J500.F35(HB16_N) U500.L20(SCTRLB-)
M_SCTRLBP: J500.F34(HB16_P) U500.M20(SCTRLB+)
MBRST0: TP4.1 U1.22(OUT00) U500.C3(MBRST00)
MBRST1: U1.24(OUT01) U500.D2(MBRST01)
MBRST2: U1.27(OUT02) U500.D3(MBRST02)
MBRST3: U1.29(OUT03) U500.E2(MBRST03)
MBRST4: U1.32(OUT04) U500.G3(MBRST04)
MBRST5: U1.34(OUT05) U500.E1(MBRST05)
MBRST6: U1.37(OUT06) U500.G2(MBRST06)
MBRST7: U1.39(OUT07) U500.G1(MBRST07)
MBRST8: TP2.1 U1.62(OUT08) U500.N3(MBRST08)
MBRST9: U1.64(OUT09) U500.M2(MBRST09)
MBRST10: U1.67(OUT10) U500.M3(MBRST10)
MBRST11: U1.69(OUT11) U500.L2(MBRST11)
MBRST12: U1.72(OUT12) U500.J3(MBRST12)
MBRST13: U1.74(OUT13) U500.L1(MBRST13)
MBRST14: U1.77(OUT14) U500.J2(MBRST14)
MBRST15: TP3.1 U1.79(OUT15) U500.J1(MBRST15)
MODE_A: R1.2 R2.1 U500.A4(MODE_A)
P3P3V2: C1.1 J500.D38(3P3V) L1.1
RES0: J500.B40(RES0)
RES1: J500.B01(RES1)
SCP_DAD_CSZ: J500.B24(DP9_C2M_P) U1.58(SCPEN/)
SCPCLK: J500.B32(DP7_C2M_P) U1.56(SCPCK) U500.A8(SCPCLK)
SCPDI: J500.B36(DP6_C2M_P) R3.1 R4.1
SCPDI_DAD: R4.2 U1.42(SCPDO)
SCPDI_RS: R3.2 U500.A9(SCPDO)
SCPDO: J500.C02(DP0_C2M_P) U1.57(SCPDI) U500.A5(SCPDI)
SCPENZ: J500.C06(DP0_M2C_P) U500.B7(SCPENZ)
VADJ: J500.E39(VADJ) J500.F40(VADJ) J500.G39(VADJ) J500.H40(VADJ)
VBIAS: C18.2 C19.2 C27.2 C30.2 D2.1(C) TP5.1 U1.9(VBIAS) U1.21(VBIAS_RAIL0) U1.30(VBIAS_RAIL1) U1.31(VBIAS_RAIL2) U1.40(VBIAS_RAIL3) U1.61(VBIAS_RAIL4) U1.70(VBIAS_RAIL5) U1.71(VBIAS_RAIL6) U1.80(VBIAS_RAIL7)
VBIAS_LHI: C10.1 C17.2 L4.1 U1.10(VBIAS_LHI)
VIO_B_M2C: J500.J39(VIO_B_M2C) J500.K40(VIO_B_M2C)
VREF_A_M2C: J500.H01(VREF_A_M2C)
VREF_B_M2C: J500.K01(VREF_B_M2C)
VRST: C15.2 C16.2 C20.2 C28.2 D1.2(A) TP7.1 U1.13(VRESET) U1.25(VRESET_RAIL0) U1.26(VRESET_RAIL1) U1.35(VRESET_RAIL2) U1.36(VRESET_RAIL3) U1.65(VRESET_RAIL4) U1.66(VRESET_RAIL5) U1.75(VRESET_RAIL6) U1.76(VRESET_RAIL7)
VRST_SWL: D1.1(C) L3.2 U1.12(VRESET_SWL)

Not connected (* = marked no-connect by the designer): J500 B12(DP7_M2C_P)* B16(DP6_M2C_P)* B17(DP6_M2C_N)* B20(GBTCLK1_M2C_P)* B21(GBTCLK1_M2C_N)* B25(DP9_C2M_N)* B28(DP8_C2M_P)* B29(DP8_C2M_N)* C10(LA06_P)* C11(LA06_N)* C14(LA10_P)* C15(LA10_N)* C18(LA14_P)* C19(LA14_N)* C30(SCL)* C31(SDA)* C34(GA0)* D01(PG_C2M)* D04(GBTCLK0_M2C_P)* D05(GBTCLK0_M2C_N)* D08(LA01_P_CC)* D09(LA01_N_CC)* D11(LA05_P)* D12(LA05_N)* D14(LA09_P)* D15(LA09_N)* D17(LA13_P)* D18(LA13_N)* D29(TCK)* D30(TDI)* D31(TDO)* D33(TMS)* D34(TRST_L)* D35(GA1)* E02(HA01_P_CC)* E03(HA01_N_CC)* E06(HA05_P)* E07(HA05_N)* E09(HA09_P)* E10(HA09_N)* E12(HA13_P)* E13(HA13_N)* E15(HA16_P)* E16(HA16_N)* E18(HA20_P)* E19(HA20_N)* E33(HB19_P)* E34(HB19_N)* E36(HB21_P)* E37(HB21_N)* F01(PG_M2C)* F04(HA00_P_CC)* F05(HA00_N_CC)* F07(HA04_P)* F08(HA04_N)* F10(HA08_P)* F11(HA08_N)* F13(HA12_P)* F14(HA12_N)* F16(HA15_P)* F17(HA15_N)* F19(HA19_P)* F20(HA19_N)* F37(HB20_P)* F38(HB20_N)* G02(CLK1_M2C_P)* G03(CLK1_M2C_N)* G06(LA00_P_CC)* G07(LA00_N_CC)* G09(LA03_P)* G10(LA03_N)* G12(LA08_P)* G13(LA08_N)* G15(LA12_P)* G16(LA12_N)* G18(LA16_P)* G19(LA16_N)* H02(PRSNT_M2C_L)* H04(CLK0_M2C_P)* H05(CLK0_M2C_N)* H07(LA02_P)* H08(LA02_N)* H10(LA04_P)* H11(LA04_N)* H13(LA07_P)* H14(LA07_N)* H16(LA11_P)* H17(LA11_N)* H19(LA15_P)* H20(LA15_N)* J06(HA03_P)* J07(HA03_N)* J09(HA07_P)* J10(HA07_N)* J12(HA11_P)* J13(HA11_N)* J15(HA14_P)* J16(HA14_N)* J18(HA18_P)* J19(HA18_N)* J21(HA22_P)* J22(HA22_N)* J36(HB18_P)* J37(HB18_N)* K07(HA02_P)* K08(HA02_N)* K10(HA06_P)* K11(HA06_N)* K13(HA10_P)* K14(HA10_N)* K16(HA17_P_CC)* K17(HA17_N_CC)* K19(HA21_P)* K20(HA21_N)* K22(HA23_P)* K23(HA23_N)* K37(HB17_P_CC)* K38(HB17_N_CC)*; U500 A3(EVCC)* A7(RESERVED_RB1)* A10(RESERVED_BB)* B2(RESERVED_VR0)* B3(RESERVED_VR1)* B10(RESERVED_TS)* E3(RESERVED_VB0)* F3(RESERVED_VB1)* K3(RESERVED_VB2)* L3(RESERVED_VB3)* P1(RESERVED_M1)* P2(RESERVED_VR2)* P3(RESERVED_VR3)* R1(RESERVED_S1)* R2(RESERVED_M0)* R3(RESERVED_A2)* R5(RESERVED_OEZ)* R6(RESERVED_RSTZ)* R10(RESERVED_TP0)* R11(RESERVED_TP2)* T1(RESERVED_S0)* T2(RESERVED_A0)* T3(RESERVED_A1)* T4(RESERVED_A3)* T5(RESERVED_STR)* T6(RESERVED_IRQZ)* T9(RESERVED_RA1)* T10(RESERVED_BA)* T11(RESERVED_TP1)*

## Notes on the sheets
sheet 2
- Revision A:
  -Initial Release
  Revision B:
  -Removed J1 (Flex cable connector)
  -Added J500 (FMC Connector)
sheet 3
- NOTE:
  Consult the DLPA200 Data Sheet for
  external component specifications.
- NOTE:
  Schottky Diode, D1, should be
  rated for 60V and 0.5 amp
  minimum current.
- NOTE:
  Care must be exersized when selecting ceramic capacitors as
  some types have much lower capacitance than rated when under
  high voltage bias.
- DLPA200 Reset Driver
sheet 4
- NOTES, UNLESS OTHERWISE SPECIFIED:
- 1.
- A "Z" suffix on a signal name indicates an active low signal.
- 2.
- All components with designators "U*", "Q*", and "D*" are electrostatic discharge sensitive.
- 3.
- All components with designators above 500 are mounted solder side of the board.
- 4.
- All resistor values are in ohms, 1/16 W and 5% unless otherwise specified.
- 5.
- All capacitor values in microfarads unless otherwise specified.
- ???
- ???
sheet 5
- FMC Connector
- LVDS Bus A:  8 Data, 1 Clock, 1 Control
- LVDS Bus B:  8 Data, 1 Clock, 1 Control
- VCC
- DLP650LE
  DMD
- SCP BUS
- 12V
- Voffset
- DLPA200
- RESET Waveform Control: Mode(1:0),
  Addr(3:1), Sel(1:0), Strobe, INTz, OEz
- MBRST(15:0)
- Oscar Guevara
- 03/10/2023
sheet 6
- Oscar Guevara
- 03/10/2023
sheet 7
- Main Controller Bus A
- Main Controller Bus B
- Total Power Transfer:
  1A at 12V
- Mode Configuration Table
- Mode
- R2 (pull-up)
- R1 (pull-down)
- Quarter Bus Mode
  Half Bus Mode
- Installed
  Not Installed
- Not Installed
  Installed
- Reference Mode
  Configuration Table
- Oscar Guevara
- 03/10/2023
